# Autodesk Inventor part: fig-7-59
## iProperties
Shininess: 64.0
Length Units: 11269
Angle Units: 11279
Time Units: 11290
Mass Units: 11283
Length Display Precision: 3
Angle Display Precision: 2
Compacted: True
Part Number: fig-7-59
Document SubType Name: Modeling
Created: 2003-08
Designer: Owner
Manufacturer: Standard
Standards Organization: Custom
Density: 1 g/cm^3
Density: 0.0
Volumn: 0.0
Area: 0.0
PropertySet Name: Model Information
Control State: 0
Master: False
Checked Out: False
Author: Owner
